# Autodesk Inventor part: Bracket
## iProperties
Shininess: 64.0
Length Units: 11269
Angle Units: 11279
Time Units: 11290
Mass Units: 11283
Length Display Precision: 3
Angle Display Precision: 2
Compacted: True
Part Number: Bracket
Document SubType Name: Modeling
Created: 2003-01
Designer: Owner
Density: 0.0
Volumn: 0.0
Area: 0.0
PropertySet Name: Model Information
Control State: 0
Master: False
Checked Out: False
Author: Owner
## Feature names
1. Extrusion1
2. Fillet1
3. Fillet2
4. Hole1
5. Rectangular Pattern1
6. Hole2
